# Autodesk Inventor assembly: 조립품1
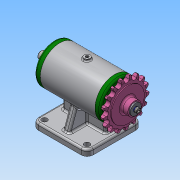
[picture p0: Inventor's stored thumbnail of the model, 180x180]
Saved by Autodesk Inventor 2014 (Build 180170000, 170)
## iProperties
Created: 2019-06
Part Number: 조립품1
Document SubType Name: Assembly
Designer: NET
Author: NET
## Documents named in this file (11)
- C:\Users\NET\Desktop\490604V1037\조립품1.iam
- C:\Users\NET\Desktop\490604V1037\부품1.ipt
- C:\Users\NET\Desktop\490604V1037\축.ipt
- C:\Users\NET\Desktop\490604V1037\베어링 6203.ipt
- C:\Users\NET\Desktop\490604V1037\커버.ipt
- C:\Users\NET\Desktop\490604V1037\오일 실 17 30 5.ipt
- C:\Users\NET\Desktop\490604V1037\키 4x4x12.ipt
- C:\Users\NET\Desktop\490604V1037\평와셔.ipt
- C:\Users\NET\Desktop\490604V1037\스프로킷.ipt
- C:\Users\NET\Desktop\490604V1037\스프링와셔.ipt
- C:\Users\NET\Desktop\490604V1037\볼트 M4.ipt
